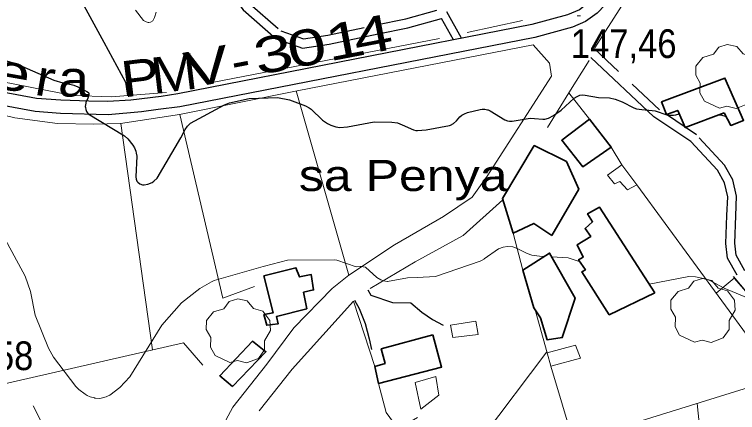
# Model space of a CAD drawing. Extents: x 480269 to 484877, y 4383588 to 4386804.
# Drawn here: x 481183 to 481403.4, y 4385428.1 to 4385549.5 of the extents above; entities that cross this region are included whole.
import ezdxf
from ezdxf.enums import TextEntityAlignment as Align

# ---------------------------------------------------------------- set-up
doc = ezdxf.new("R2010")
doc.units = 0
doc.header["$LTSCALE"] = 3.8
doc.linetypes.add('LONG_DASHED', pattern=[7.5, 6, -1.5])
doc.linetypes.add('MEDIUM_DASHED', pattern=[4.5, 3, -1.5])
for name, color, linetype, lineweight in [('25', 7, 'LONG_DASHED', 25), ('29', 7, 'Continuous', 13), ('36', 7, 'Continuous', 25), ('38', 7, 'Continuous', 25), ('47', 7, 'Continuous', 35), ('51', 7, 'Continuous', 13), ('7', 7, 'Continuous', 13), ('8', 7, 'Continuous', 25), ('9', 7, 'Continuous', 13)]:
    doc.layers.add(name, color=color, linetype=linetype, lineweight=lineweight)
doc.layers.add('5', color=7, linetype='Continuous')

msp = doc.modelspace()

# ---------------------------------------------------------------- linework, layer by layer
at = {"layer": '25'}
msp.add_lwpolyline([(481199.53, 4385618.91), (481201.89, 4385612.64), (481202.98, 4385605.05), (481203.22, 4385599.97), (481203.49, 4385592.15), (481201.4, 4385581.35), (481198.13, 4385578.49), (481195.48, 4385574.35), (481197.26, 4385568.2), (481203.55, 4385553.36), (481210.26, 4385541.08), (481216.82, 4385528.89), (481217.5, 4385524.78)], dxfattribs=at)
at = {"layer": '29'}
for points in [[(481397.85, 4385520.95), (481393.31, 4385523.07), (481391.9, 4385525.61), (481392, 4385528.59), (481390.63, 4385531), (481390.67, 4385533.75), (481392.83, 4385536.35), (481396.02, 4385537.35), (481397.67, 4385539.54), (481400.24, 4385540.37), (481403.1, 4385539.72), (481405.05, 4385537.45), (481407.86, 4385536.63), (481409.99, 4385533.78), (481410.23, 4385530.65), (481408.35, 4385527.5), (481408.35, 4385524.82), (481406.53, 4385522.21), (481402.91, 4385520.87), (481400.14, 4385521.5)], [(481390.26, 4385449.6), (481385.72, 4385451.72), (481384.31, 4385454.26), (481384.41, 4385457.24), (481383.04, 4385459.65), (481383.08, 4385462.4), (481385.24, 4385465), (481388.43, 4385466), (481390.08, 4385468.19), (481392.65, 4385469.02), (481395.51, 4385468.37), (481397.46, 4385466.1), (481400.27, 4385465.28), (481402.4, 4385462.43), (481402.64, 4385459.3), (481400.76, 4385456.15), (481400.76, 4385453.47), (481398.94, 4385450.86), (481395.32, 4385449.52), (481392.55, 4385450.15)], [(481248.68, 4385443.4), (481244.14, 4385445.52), (481242.73, 4385448.06), (481242.83, 4385451.04), (481241.46, 4385453.45), (481241.5, 4385456.2), (481243.66, 4385458.8), (481246.85, 4385459.8), (481248.5, 4385461.99), (481251.07, 4385462.82), (481253.93, 4385462.17), (481255.88, 4385459.9), (481258.69, 4385459.08), (481260.82, 4385456.23), (481261.06, 4385453.1), (481259.18, 4385449.95), (481259.18, 4385447.27), (481257.36, 4385444.66), (481253.74, 4385443.32), (481250.97, 4385443.95)]]:
    msp.add_lwpolyline(points, close=True, dxfattribs=at)
at = {"layer": '36'}
for points in [[(481532.74, 4385795.43), (481541.49, 4385752.66), (481546.75, 4385724), (481547.82, 4385715.36), (481547.68, 4385711.2), (481546.25, 4385705.89), (481540.95, 4385698.46), (481469.12, 4385643.89), (481413.83, 4385603.2), (481387.79, 4385580.04), (481378.21, 4385569.43), (481368.09, 4385557.76), (481360.55, 4385549.93), (481356.99, 4385547.39), (481353.06, 4385545.63), (481341.54, 4385542.48), (481233.43, 4385521.3), (481226.84, 4385520.47), (481221.75, 4385519.81), (481211.59, 4385518.94), (481197.06, 4385519.31), (481189.31, 4385519.87), (481157.81, 4385525.71)], [(481528.8, 4385794.63), (481537.55, 4385751.89), (481542.78, 4385723.39), (481543.79, 4385715.19), (481543.68, 4385711.79), (481542.56, 4385707.64), (481538.04, 4385701.29), (481466.72, 4385647.1), (481411.3, 4385606.32), (481384.96, 4385582.9), (481375.2, 4385572.09), (481365.12, 4385560.48), (481358.05, 4385553.13), (481355.22, 4385550.94), (481351.5, 4385549.38), (481340.63, 4385546.4), (481232.83, 4385525.27), (481227.75, 4385524.48), (481218.5, 4385523.39), (481211.46, 4385522.97), (481205.65, 4385523.06), (481197.15, 4385523.39), (481189.77, 4385523.87), (481158.52, 4385529.67)]]:
    msp.add_lwpolyline(points, dxfattribs=at)
at = {"layer": '38', "linetype": 'MEDIUM_DASHED'}
msp.add_line((481319.26, 4385542.21), (481314.75, 4385550.27), dxfattribs=at)
at = {"layer": '38'}
msp.add_line((481316.81, 4385541.73), (481313.16, 4385548.25), dxfattribs=at)
at = {"layer": '38', "linetype": 'MEDIUM_DASHED'}
for points in [[(481111.25, 4385537.94), (481107.24, 4385554.33), (481103.84, 4385564.38), (481101.02, 4385571.24), (481100.4, 4385574.69), (481106.32, 4385578.09), (481157.8, 4385602.05), (481211.79, 4385627.86), (481215.72, 4385628.21), (481217.83, 4385627.15), (481221.21, 4385624.41), (481230.48, 4385610.08), (481238.24, 4385596.51), (481242.56, 4385580.85), (481248.31, 4385561.36), (481254.8, 4385552.77), (481264.19, 4385544.5), (481271.08, 4385542.08), (481278.48, 4385543.14), (481293.29, 4385546.34), (481302.26, 4385548.13), (481311.76, 4385550.76)], [(481405.62, 4385471.36), (481402.9, 4385476.06), (481402.51, 4385479.72), (481402.79, 4385488.07), (481403.04, 4385494.14), (481401.91, 4385499.1), (481399.42, 4385503.57), (481390.86, 4385512.77), (481379.58, 4385520.38), (481359.62, 4385539.16)]]:
    msp.add_lwpolyline(points, dxfattribs=at)
at = {"layer": '38'}
for points in [[(481114.25, 4385537.41), (481109.92, 4385555.11), (481106.46, 4385565.35), (481103.71, 4385572.03), (481103.49, 4385573.25), (481107.61, 4385575.61), (481158.99, 4385599.52), (481212.54, 4385625.13), (481215.18, 4385625.36), (481216.31, 4385624.8), (481219.11, 4385622.52), (481228.09, 4385608.63), (481235.64, 4385595.43), (481239.87, 4385580.09), (481245.78, 4385560.09), (481252.75, 4385550.86), (481262.76, 4385542.05), (481270.8, 4385539.22), (481278.97, 4385540.4), (481293.86, 4385543.61), (481302.91, 4385545.42), (481313.16, 4385548.25)], [(481403.29, 4385470.02), (481400.3, 4385475.2), (481399.82, 4385479.62), (481400.11, 4385488.17), (481400.35, 4385493.89), (481399.38, 4385498.13), (481397.24, 4385501.98), (481389.1, 4385510.72), (481377.9, 4385518.28), (481358.7, 4385536.35)], [(481451.61, 4385418.73), (481441.07, 4385430.49), (481430.78, 4385440.39), (481418.44, 4385451.88), (481408.48, 4385461.95), (481402.11, 4385469.58)], [(481290.73, 4385465.56), (481291.62, 4385463.92), (481298.24, 4385461.67), (481303.76, 4385461.56), (481307.2, 4385458.74), (481310.39, 4385456.47), (481313.66, 4385454.78)], [(481286.65, 4385462.43), (481288.07, 4385459.87), (481289.9, 4385455.31), (481291.12, 4385450.56), (481291.83, 4385447.33)]]:
    msp.add_lwpolyline(points, dxfattribs=at)
at = {"layer": '47'}
for points in [[(481399.25, 4385519.52), (481401.3, 4385515.67), (481405.21, 4385517.17), (481399.49, 4385530.08), (481380.23, 4385522.82), (481381.66, 4385519.01), (481385.15, 4385520.22), (481387.43, 4385515.02)], [(481358.28, 4385517.54), (481349.81, 4385511.15), (481356.19, 4385503.05), (481364.8, 4385509.03)], [(481346.75, 4385482.08), (481354.97, 4385496.18), (481351.2, 4385504.64), (481341.43, 4385509.54), (481331.73, 4385493.34), (481334.95, 4385482.86), (481341.28, 4385485.79)], [(481378.13, 4385464.61), (481364.29, 4385457.93), (481355.88, 4385470.99), (481356.99, 4385471.65), (481354.94, 4385474.72), (481356.32, 4385475.52), (481354.49, 4385479.29), (481358.61, 4385481.85), (481356.9, 4385484.23), (481359.19, 4385486.29), (481357.67, 4385488.76), (481361.31, 4385490.7)], [(481337.92, 4385471.52), (481346.06, 4385476.74), (481353.9, 4385463.05), (481349.94, 4385451.01), (481345.34, 4385450.34), (481343.31, 4385457.03), (481341.25, 4385460.1)], [(481272.09, 4385459.7), (481271.12, 4385464.8), (481274.16, 4385465.52), (481273.47, 4385470.18), (481269.84, 4385469.46), (481268.77, 4385472.25), (481259.02, 4385469.8), (481261.89, 4385458.55), (481259.05, 4385458.05), (481259.91, 4385454.73), (481263.34, 4385455.16), (481262.85, 4385457.39)], [(481310.56, 4385451.83), (481313.19, 4385441.99), (481293.98, 4385437.02), (481292.79, 4385442.14), (481295.96, 4385443.1), (481294.79, 4385447.57)], [(481249.5, 4385436.05), (481245.6, 4385439.34), (481255.61, 4385449.88), (481259.63, 4385446.66)]]:
    msp.add_lwpolyline(points, close=True, dxfattribs=at)
at = {"layer": '47', "lineweight": 13}
for points in [[(481372.71, 4385497.59), (481369.8, 4385496.04), (481367.52, 4385498.58), (481365.82, 4385497.81), (481363.78, 4385500.52), (481368.09, 4385503.65)], [(481316.64, 4385450.99), (481315.9, 4385454.79), (481323.62, 4385455.97), (481324.29, 4385451.92)], [(481346.48, 4385442.32), (481345.3, 4385446.35), (481353.96, 4385448.71), (481355.53, 4385444.74)], [(481306.85, 4385429.14), (481305.16, 4385437.32), (481311.42, 4385439.1), (481312.36, 4385433.39)]]:
    msp.add_lwpolyline(points, close=True, dxfattribs=at)
at = {"layer": '51'}
for p, q in [((481337.85, 4385547.69), (481321.02, 4385543.94)), ((481312.53, 4385542.18), (481243.78, 4385528.83)), ((481358.15, 4385535.48), (481351.9, 4385525.64)), ((481284.93, 4385470.04), (481268.83, 4385526.19)), ((481225.1, 4385447.26), (481215.48, 4385516.24)), ((481368.09, 4385503.65), (481364.8, 4385509.03)), ((481337.92, 4385471.52), (481334.95, 4385482.86)), ((481341.68, 4385459.47), (481345.3, 4385446.35)), ((481391.1, 4385430.92), (481396.74, 4385376.54))]:
    msp.add_line(p, q, dxfattribs=at)
for points in [[(481571.15, 4385430.52), (481521.63, 4385485.21), (481474.7, 4385536.56), (481414.19, 4385601.57), (481394.98, 4385584.15), (481379.56, 4385569.01), (481368.93, 4385553.46), (481359.87, 4385539.34)], [(481229.34, 4385525.73), (481212.45, 4385524.36), (481200.78, 4385524.77), (481122.73, 4385540.02)], [(481169.86, 4385495.15), (481163.25, 4385522.74), (481183.1, 4385517.94), (481196.18, 4385516.23), (481207.26, 4385516.02), (481215.39, 4385516.23), (481233.27, 4385518.95), (481269.15, 4385526.25), (481341.05, 4385540.26), (481346.05, 4385534.66)], [(481195.81, 4385368.29), (481211.41, 4385368.01), (481213.7, 4385374.36), (481220.4, 4385382.08), (481227.61, 4385389.86), (481235.77, 4385403.85), (481243.78, 4385418.97), (481249.59, 4385429.81), (481259.98, 4385442.89), (481268.12, 4385454), (481279.82, 4385465.98), (481284.94, 4385470.05), (481298.86, 4385479.3), (481313.75, 4385487.91), (481322.51, 4385493.76), (481327.1, 4385500.21), (481346.7, 4385530.71), (481346.05, 4385534.66)], [(481358.28, 4385517.54), (481351.9, 4385525.64), (481345.45, 4385515)], [(481233.4, 4385518.98), (481246.48, 4385463.02), (481256.21, 4385466.53)], [(481353.38, 4385419.22), (481415.82, 4385438.58), (481372.71, 4385497.59)], [(481331.83, 4385493.01), (481319.75, 4385482.07), (481305.13, 4385474.11), (481291.4, 4385465.96)], [(481396.85, 4385464.57), (481402.37, 4385469.07), (481423.28, 4385445.25), (481420.17, 4385441.89)], [(481257.56, 4385428.66), (481267.6, 4385441.34), (481286.3, 4385462.05), (481292.79, 4385442.14)], [(481240.43, 4385442.6), (481234.54, 4385449.42), (481178.56, 4385436.6)], [(481345.21, 4385446.68), (481325.69, 4385420.67), (481314.14, 4385405.05), (481275.34, 4385371.23)], [(481346.48, 4385442.32), (481364.24, 4385382.84), (481386.46, 4385378.97), (481404.15, 4385374.77)], [(481293.98, 4385437.02), (481296.3, 4385428.17), (481299.95, 4385423.16), (481305.82, 4385426.63)], [(481188.68, 4385430.23), (481195.97, 4385415.81), (481199.46, 4385403.11), (481200.42, 4385395.07)]]:
    msp.add_lwpolyline(points, dxfattribs=at)
at = {"layer": '7'}
msp.add_line((481354.5, 4385549.03), (481355.5, 4385549.03), dxfattribs=at)
at = {"layer": '8'}
for points in [[(481175.12, 4385536.95), (481183.65, 4385534.47), (481194.98, 4385529.47), (481197.73, 4385528.65), (481200.31, 4385528.18), (481201.12, 4385527.95), (481202.37, 4385527.43), (481205.12, 4385526.02), (481205.54, 4385525.7), (481205.61, 4385525.59), (481205.66, 4385525.47), (481205.67, 4385524.95), (481205.38, 4385524.02), (481204.79, 4385522.65), (481204.74, 4385522.49), (481204.63, 4385521.97), (481204.61, 4385521.44), (481204.65, 4385521.12), (481204.79, 4385520.48), (481205.01, 4385519.87), (481205.17, 4385519.6), (481205.53, 4385519.19), (481216.58, 4385512.44), (481217.57, 4385511.54), (481219.1, 4385509.69), (481219.63, 4385508.8), (481220, 4385507.82), (481220.16, 4385507.21), (481220.28, 4385506.26), (481220.06, 4385500.02), (481220.12, 4385499.28), (481220.34, 4385498.67), (481220.45, 4385498.52), (481220.58, 4385498.36), (481221.23, 4385497.87), (481222.08, 4385497.57), (481222.33, 4385497.55), (481222.6, 4385497.55), (481223.63, 4385497.76), (481224.99, 4385498.31), (481225.52, 4385498.63), (481226.47, 4385499.54), (481233.74, 4385511.84), (481235.05, 4385514.41), (481235.78, 4385515.39), (481236.72, 4385516.32), (481247.05, 4385521.94), (481248.57, 4385522.59), (481254.54, 4385523.83), (481263.22, 4385524.16), (481266.85, 4385523.43), (481271.69, 4385521.67), (481272.86, 4385521.01), (481273.44, 4385520.58), (481276.91, 4385517.25), (481278.43, 4385516.23), (481279.42, 4385515.73), (481280.93, 4385515.23), (481282.19, 4385515.03), (481284.51, 4385515.26), (481292.62, 4385516.72), (481298.01, 4385516.68), (481299.71, 4385516.41), (481301.16, 4385515.88), (481304.63, 4385514.31), (481305.34, 4385514.15), (481305.83, 4385514.12), (481308.49, 4385514.34), (481315.56, 4385515.61), (481315.92, 4385515.73), (481316.83, 4385516.2)], [(481316.83, 4385516.2), (481317.69, 4385517.03), (481318.73, 4385518.25), (481319.37, 4385518.79), (481320.12, 4385519.24), (481321.05, 4385519.63), (481324.95, 4385520.52), (481325.51, 4385520.57), (481326.33, 4385520.57), (481327.18, 4385520.42), (481327.35, 4385520.37), (481327.93, 4385520.14), (481332.48, 4385517.4), (481333.27, 4385517.11), (481333.87, 4385516.98), (481334.73, 4385516.96), (481340.12, 4385517.83), (481341.47, 4385517.79), (481344, 4385517.54), (481344.66, 4385517.6), (481345.74, 4385517.89), (481347.28, 4385518.64), (481349.57, 4385520.29), (481353.62, 4385523.95), (481354.47, 4385524.49), (481355.33, 4385524.87), (481356.22, 4385524.96), (481356.9, 4385524.9), (481361.03, 4385524.14), (481364.34, 4385524.03), (481366.08, 4385523.67), (481368.24, 4385522.84), (481371.73, 4385521.05), (481372.6, 4385520.73), (481374.16, 4385520.49), (481377.35, 4385520.25), (481378.25, 4385520.08), (481381.83, 4385518.94), (481382.79, 4385518.75), (481383.82, 4385518.79), (481384.58, 4385518.94), (481385.59, 4385519.23)], [(481397.68, 4385518.92), (481398.53, 4385518.78), (481399.86, 4385518.37)]]:
    msp.add_lwpolyline(points, dxfattribs=at)
at = {"layer": '9'}
for points in [[(481226.2, 4385550.18), (481225.73, 4385548.54), (481225.23, 4385547.53), (481225.15, 4385547.5), (481224.51, 4385547.16), (481224.02, 4385547.02), (481223.88, 4385547.02), (481223.73, 4385547.03), (481223.17, 4385547.22), (481222.37, 4385547.63), (481222.32, 4385547.65), (481219.91, 4385550.75)], [(481205.18, 4385433.35), (481204.54, 4385433.72), (481202.62, 4385435.15), (481201.73, 4385436.03), (481194.94, 4385445.02), (481193.4, 4385447.77), (481189.38, 4385457.81), (481187.91, 4385465), (481186.32, 4385469.75), (481179.6, 4385482.14)], [(481344.42, 4385475.69), (481343, 4385475.76), (481340.69, 4385476.12), (481339.23, 4385476.61), (481336.2, 4385478.12), (481334.85, 4385478.61), (481333.31, 4385478.76), (481331.99, 4385478.55), (481330.47, 4385478.07), (481326.19, 4385474.95), (481326.12, 4385474.91), (481324.9, 4385474.31), (481311.3, 4385469.59), (481305.7, 4385469.29), (481302.83, 4385469.16), (481296.69, 4385468.08), (481296.57, 4385468.09), (481295.49, 4385468.32), (481294.71, 4385468.64), (481293.47, 4385469.35), (481289.96, 4385472.41), (481289.92, 4385472.48), (481288.64, 4385472.65), (481288.48, 4385472.64), (481288.38, 4385472.62), (481287.12, 4385472.59), (481281.23, 4385474.55), (481280.4, 4385474.71), (481266.2, 4385474.6), (481259.17, 4385472.75), (481258.82, 4385472.61), (481243.92, 4385468.4), (481243.09, 4385468.03), (481239.53, 4385465.97), (481233.95, 4385461.58), (481227.94, 4385454.77), (481218.21, 4385439), (481215.15, 4385435.8), (481212.09, 4385433.47), (481211.41, 4385433.13), (481211, 4385432.97), (481209.07, 4385432.45), (481207.73, 4385432.48), (481207.56, 4385432.52), (481207.38, 4385432.59), (481206.1, 4385432.95), (481205.18, 4385433.35)], [(481355.37, 4385474.07), (481355.1, 4385474.18), (481351.73, 4385475.31), (481346.73, 4385475.57)], [(481406.56, 4385463.03), (481399.27, 4385466.09), (481394.89, 4385468.41), (481393.88, 4385468.78), (481390.58, 4385469.52), (481390.57, 4385469.52), (481388.55, 4385469.56), (481376.4, 4385467.29)]]:
    msp.add_lwpolyline(points, dxfattribs=at)

# ---------------------------------------------------------------- texts
at = {"layer": '5'}
for s, rotation, width, p in [('4', 10.91, 1.45, (481293.18, 4385537.9)), ('1', 10.91, 1.45, (481284.75, 4385536.27)), ('0', 10.864, 1.45, (481273.1, 4385534.03)), ('3', 10.864, 1.45, (481262.95, 4385532.09)), ('V', 10.864, 1.4, (481242.77, 4385528.21)), ('M', 6.906, 1.15, (481232.3, 4385526.11)), ('P', 6.906, 1.2, (481222.07, 4385524.88)), ('e', 349.99, 1.35, (481181.46, 4385526.39)), ('r', 349.99, 1.15, (481191.6, 4385524.61)), ('-', 10.864, 1.2, (481252.84, 4385530.14)), ('a', 358.914, 1.15, (481200.96, 4385524.42))]:
    msp.add_text(s, height=10.99, rotation=rotation, dxfattribs=dict(at, width=width)).set_placement(p, align=Align.CENTER)
at = {"layer": '5', "width": 1.2}
msp.add_text('sa Penya', height=9.5, dxfattribs=at).set_placement((481269.69, 4385495.66))
at = {"layer": '7', "width": 0.9}
for s, p in [('147,46', (481352.56, 4385536.22)), ('158,58', (481156.56, 4385441.07))]:
    msp.add_text(s, height=8.75, dxfattribs=at).set_placement(p)

doc.saveas('drawing.dxf')
